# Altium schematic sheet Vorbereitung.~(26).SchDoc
size A4
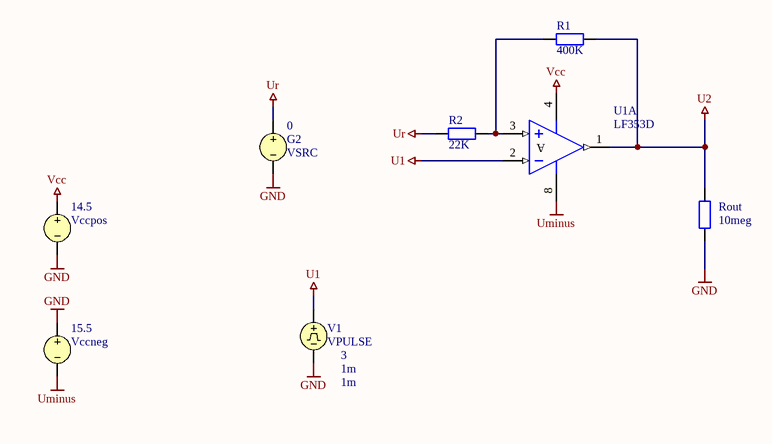
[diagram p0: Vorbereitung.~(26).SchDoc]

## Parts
G2  VSRC  value 0
R1  value 400K  [AXIAL-0.4]  (hidden comment: Res2)
R2  value 22K  [AXIAL-0.4]  (hidden comment: Res2)
Rout  value 10meg  [AXIAL-0.4]  (hidden comment: Res2)
U1  LF353D  [D008_L]  (part A of 2)
V1  VPULSE  AC Magnitude: 3  Rise Time: 1m
Vccneg  value 15.5  (hidden comment: VSRC)
Vccpos  value 14.5  (hidden comment: VSRC)

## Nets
GND: G2.2 Rout.1 V1.2 Vccneg.1 Vccpos.2
U1: U1.2(IN-) V1.1
U2: R1.1 Rout.2 U1.1(OUT)
Uminus: U1.8(V+) Vccneg.2
Ur: G2.1 R2.2
Vcc: U1.4(V-) Vccpos.1
NetR1_2: R1.2 R2.1 U1.3(IN+)

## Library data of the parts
G2 Vccneg Vccpos = VSRC: Voltage Source; Note: PCB Footprint - Not required
R1 R2 Rout = Res2: Resistor
U1 = LF353D: Dual Operational Amplifier
V1 = VPULSE: Pulse Voltage Source; Note: PCB Footprint - Not required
